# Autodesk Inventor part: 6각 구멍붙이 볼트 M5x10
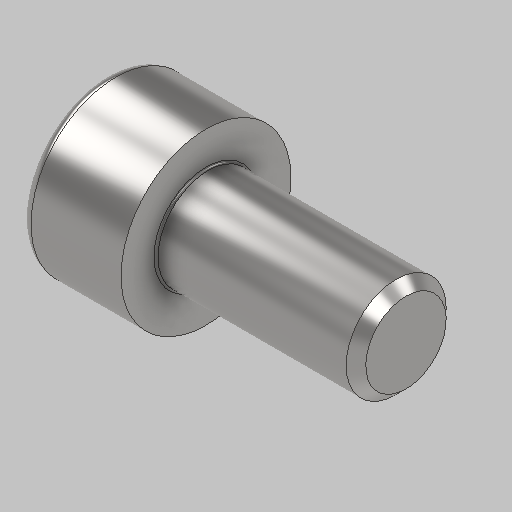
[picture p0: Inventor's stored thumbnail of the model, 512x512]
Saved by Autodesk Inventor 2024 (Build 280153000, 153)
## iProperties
Created: 2026-01
Part Number: 6각 구멍붙이 볼트 M5x10
Material: 강철, 연강
Description: 6각머리 태핑 나사
Document SubType Name: Modeling
Designer: 2-10
Density: 7.85 g/cm^3
Appearance: 기본값
Author: jhkim
Sending System: Autodesk Inventor 2026
Preprocessor: ST-DEVELOPER v20.1
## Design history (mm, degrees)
feature "Solid1"
node "솔리드1"
